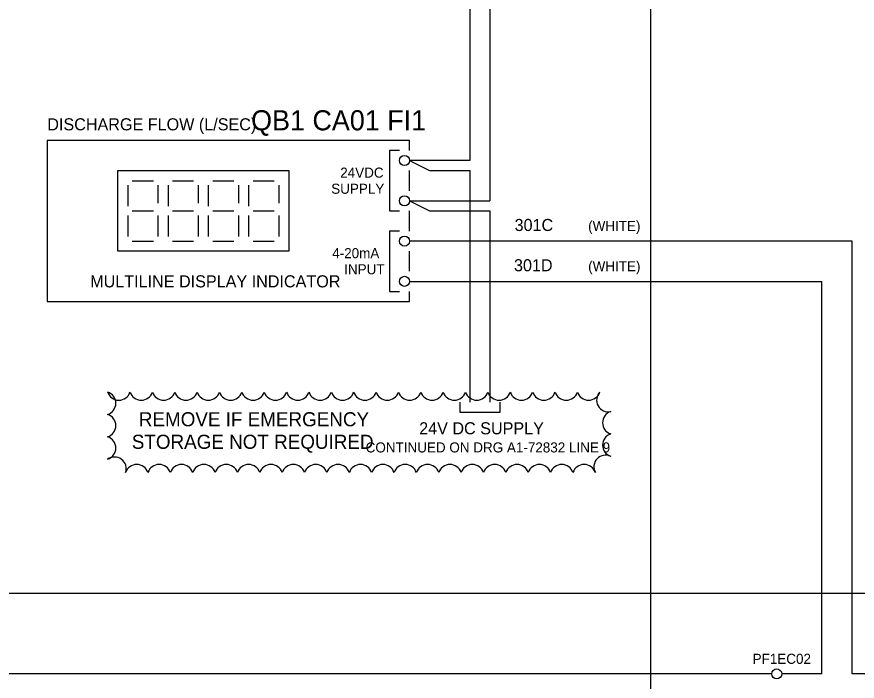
# Model space of a CAD drawing. Extents: x 0 to 841, y 0 to 594.
# Drawn here: x 382.4 to 591.2, y 140.7 to 305.7 of the extents above; entities that cross this region are included whole.
import ezdxf

# ---------------------------------------------------------------- set-up
doc = ezdxf.new("R2010")
doc.units = 0
for name, color, linetype in [('Level 1', 7, 'Continuous'), ('Level 10', 7, 'Continuous'), ('Level 2', 7, 'Continuous')]:
    doc.layers.add(name, color=color, linetype=linetype)

msp = doc.modelspace()

# ---------------------------------------------------------------- linework, layer by layer
at = {"layer": 'Level 1'}
for p, q in [((540, 57), (540, 572.5)), ((495, 387.5), (495, 270)), ((500, 377.5), (500, 260)), ((495, 270), (480, 270)), ((480, 270), (485, 267.5)), ((485, 267.5), (495, 267.5)), ((495, 267.5), (495, 210)), ((480, 260), (500, 260)), ((480, 260), (485, 257.5)), ((485, 257.5), (500, 257.5)), ((500, 257.5), (500, 210)), ((590, 250), (480, 250)), ((590, 142.5), (590, 250)), ((480, 240), (582.5, 240)), ((582.5, 142.5), (582.5, 240)), ((640, 162.5), (315, 162.5)), ((570, 142.5), (315, 142.5)), ((570, 142.5), (570, 142.5)), ((582.5, 142.5), (572.5, 142.5)), ((572.5, 142.5), (572.5, 142.5)), ((640, 142.5), (590, 142.5))]:
    msp.add_line(p, q, dxfattribs=at)
for points in [[(477.5, 272.5), (475, 272.5), (475, 257.5), (477.5, 257.5)], [(477.5, 252.5), (475, 252.5), (475, 237.5), (477.5, 237.5)], [(492.5, 210), (492.5, 207.5), (502.5, 207.5), (502.5, 210)]]:
    msp.add_lwpolyline(points, dxfattribs=at)
msp.add_lwpolyline([(407.5, 267.5), (450, 267.5), (450, 247.5), (407.5, 247.5)], close=True, dxfattribs=at)
for centre, start, end in [((407.78, 213.38), 197.5, 342.5), ((404.12, 209.72), 287.5, 72.5), ((413.34, 213.38), 197.5, 342.5), ((418.9, 213.38), 197.5, 342.5), ((424.45, 213.38), 197.5, 342.5), ((430.01, 213.38), 197.5, 342.5), ((435.57, 213.38), 197.5, 342.5), ((441.13, 213.38), 197.5, 342.5), ((446.69, 213.38), 197.5, 342.5), ((452.25, 213.38), 197.5, 342.5), ((457.8, 213.38), 197.5, 342.5), ((463.36, 213.38), 197.5, 342.5), ((468.92, 213.38), 197.5, 342.5), ((474.48, 213.38), 197.5, 342.5), ((480.04, 213.38), 197.5, 342.5), ((485.6, 213.38), 197.5, 342.5), ((491.15, 213.38), 197.5, 342.5), ((496.71, 213.38), 197.5, 342.5), ((502.27, 213.38), 197.5, 342.5), ((507.83, 213.38), 197.5, 342.5), ((513.39, 213.38), 197.5, 342.5), ((518.95, 213.38), 197.5, 342.5), ((524.51, 213.38), 197.5, 342.5), ((529.41, 210.51), 136.7666, 281.7666), ((404.12, 204.16), 287.5, 72.5), ((530.88, 204.87), 107.5, 252.5), ((404.12, 198.6), 287.5, 72.5), ((530.88, 199.32), 107.5, 252.5), ((406.7, 193.46), 340.7573, 125.7573), ((528.73, 193.92), 64.0891, 209.0891), ((412.23, 191.62), 17.5, 162.5), ((417.79, 191.62), 17.5, 162.5), ((423.35, 191.62), 17.5, 162.5), ((428.91, 191.62), 17.5, 162.5), ((434.47, 191.62), 17.5, 162.5), ((440.03, 191.62), 17.5, 162.5), ((445.58, 191.62), 17.5, 162.5), ((451.14, 191.62), 17.5, 162.5), ((456.7, 191.62), 17.5, 162.5), ((462.26, 191.62), 17.5, 162.5), ((467.82, 191.62), 17.5, 162.5), ((473.38, 191.62), 17.5, 162.5), ((478.93, 191.62), 17.5, 162.5), ((484.49, 191.62), 17.5, 162.5), ((490.05, 191.62), 17.5, 162.5), ((495.61, 191.62), 17.5, 162.5), ((501.17, 191.62), 17.5, 162.5), ((506.73, 191.62), 17.5, 162.5), ((512.28, 191.62), 17.5, 162.5), ((517.84, 191.62), 17.5, 162.5), ((523.4, 191.62), 17.5, 162.5)]:
    msp.add_arc(centre, 2.91, start, end, dxfattribs=at)
at = {"layer": 'Level 10'}
for centre in [(478.75, 270), (478.75, 260), (478.75, 250), (478.75, 240), (571.25, 142.5)]:
    msp.add_circle(centre, 1.25, dxfattribs=at)
at = {"layer": 'Level 2'}
for p, q in [((410, 263.88), (410, 258.63)), ((411.13, 265), (416.37, 265)), ((417.5, 263.88), (417.5, 259.38)), ((420, 263.88), (420, 258.63)), ((421.13, 265), (426.37, 265)), ((427.5, 263.88), (427.5, 259.38)), ((430, 263.88), (430, 258.63)), ((431.13, 265), (436.37, 265)), ((437.5, 263.88), (437.5, 259.38)), ((440, 263.88), (440, 258.63)), ((441.13, 265), (446.37, 265)), ((447.5, 263.88), (447.5, 259.38)), ((411.13, 257.5), (416.37, 257.5)), ((421.13, 257.5), (426.37, 257.5)), ((431.13, 257.5), (436.37, 257.5)), ((441.13, 257.5), (446.37, 257.5)), ((410, 256.38), (410, 251.13)), ((417.5, 256.38), (417.5, 251.13)), ((420, 256.38), (420, 251.13)), ((427.5, 256.38), (427.5, 251.13)), ((430, 256.38), (430, 251.13)), ((437.5, 256.38), (437.5, 251.13)), ((440, 256.38), (440, 251.13)), ((447.5, 256.38), (447.5, 251.13)), ((411.13, 250), (416.37, 250)), ((421.13, 250), (426.37, 250)), ((431.13, 250), (436.37, 250)), ((441.13, 250), (446.37, 250))]:
    msp.add_line(p, q, dxfattribs=at)
for points in [[(480, 272.5), (480, 275), (390, 275), (390, 235)], [(480, 262.5), (480, 267.5)], [(480, 252.5), (480, 257.5)], [(480, 242.5), (480, 247.5)], [(390, 235), (480, 235), (480, 237.5)]]:
    msp.add_lwpolyline(points, dxfattribs=at)

# ---------------------------------------------------------------- texts
at = {"layer": 'Level 1'}
for s, height, p in [('QB1 CA01 FI1', 5, (440.65, 277.5)), ('DISCHARGE FLOW (L/SEC)', 3, (390, 277.5)), ('24VDC', 2.5, (462.79, 265.75)), ('SUPPLY', 2.5, (460.55, 261.75)), ('301C', 3, (506.12, 252.5)), ('(WHITE)', 2.5, (524.4, 252.5)), ('4-20mA', 2.5, (460.8, 245.75)), ('301D', 3, (505.97, 242.5)), ('(WHITE)', 2.5, (524.4, 242.5)), ('INPUT', 2.5, (463.78, 241.75)), ('REMOVE IF EMERGENCY', 3.5, (412.75, 204)), ('24V DC SUPPLY', 3, (482.41, 202)), ('STORAGE NOT REQUIRED', 3.5, (411, 198.4)), ('CONTINUED ON DRG A1-72832 LINE 9', 2.5, (469.11, 197.5)), ('PF1EC02', 2.5, (565.27, 145))]:
    msp.add_text(s, height=height, dxfattribs=at).set_placement(p)
at = {"layer": 'Level 2'}
msp.add_text('MULTILINE DISPLAY INDICATOR', height=3, dxfattribs=at).set_placement((400.66, 238.5))

doc.saveas('drawing.dxf')
